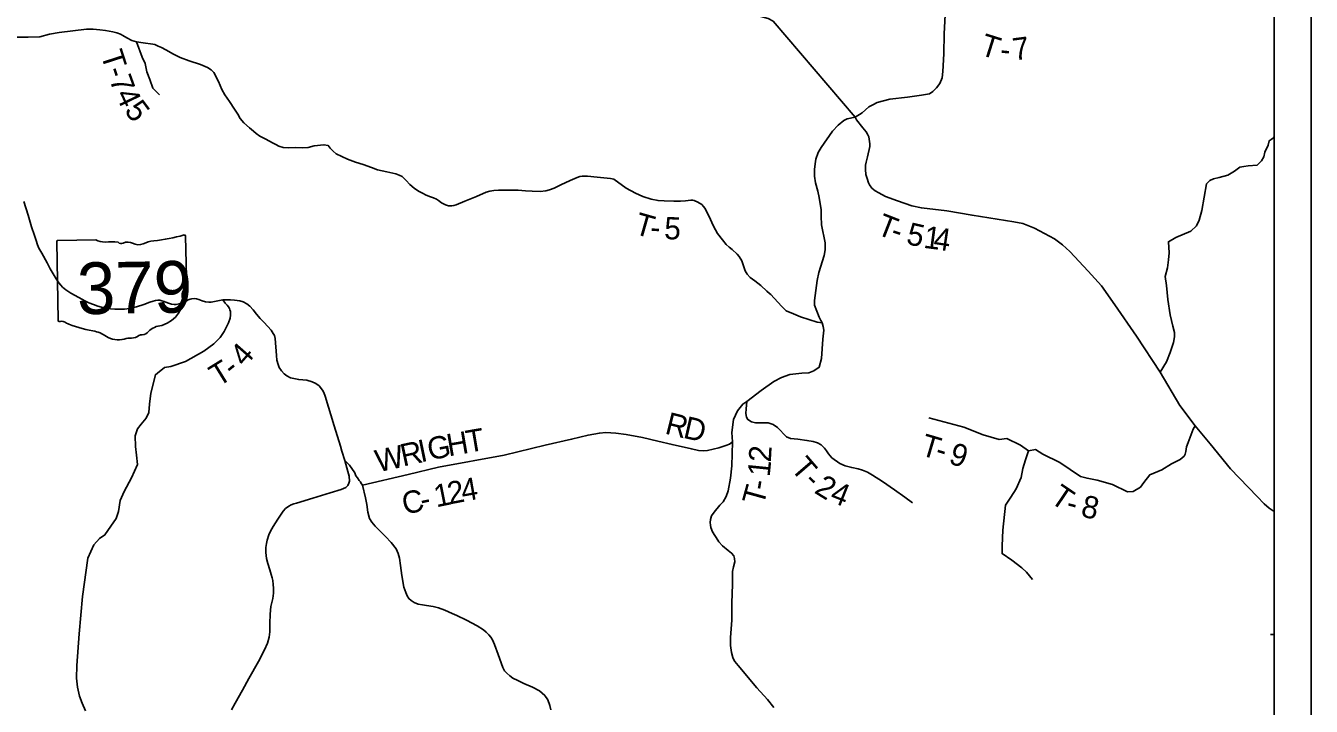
# Model space of a CAD drawing. Extents: x 0 to 2329303, y 0 to 694397.
# Drawn here: x 5.532 to 9, y 18.113 to 19.946 of the extents above; entities that cross this region are included whole.
import ezdxf

# ---------------------------------------------------------------- set-up
doc = ezdxf.new("R2010")
doc.units = 0
for name, color, linetype in [('GM_X_County_Road', 7, 'Continuous'), ('GM_X_County_Road_Text', 7, 'Continuous'), ('GM_X_State_Route', 7, 'Continuous'), ('GM_X_State_Shield', 7, 'Continuous'), ('GM_X_Township_Road', 7, 'Continuous'), ('GM_X_Township_Road_Text', 7, 'Continuous'), ('GM_X_Township_ROW', 7, 'Continuous'), ('SH_Data', 7, 'Continuous')]:
    doc.layers.add(name, color=color, linetype=linetype)

msp = doc.modelspace()

# ---------------------------------------------------------------- linework, layer by layer
at = {"layer": 'GM_X_County_Road'}
for points in [[(6.4411, 18.7082), (6.5643, 18.7373), (6.6462, 18.7565), (6.8229, 18.7894), (6.9332, 18.8158), (7.0048, 18.8321), (7.0492, 18.8434), (7.0798, 18.8488), (7.0976, 18.8503), (7.1241, 18.8485), (7.1519, 18.8452), (7.1959, 18.8363), (7.2372, 18.8271), (7.2758, 18.8178), (7.3279, 18.806), (7.3471, 18.8021), (7.3605, 18.8007), (7.3713, 18.8018), (7.4016, 18.809), (7.4211, 18.8147), (7.4309, 18.8185), (7.4389, 18.8248), (7.4371, 18.8504), (7.4416, 18.8853), (7.452, 18.9084), (7.4663, 18.9265), (7.4778, 18.9337), (7.5159, 18.9637), (7.5505, 18.9878), (7.5706, 18.9984), (7.5931, 19.0061), (7.6262, 19.0098), (7.645, 19.011), (7.6583, 19.0167), (7.6728, 19.0261), (7.6788, 19.0493), (7.6828, 19.1016), (7.6848, 19.1263), (7.6835, 19.1361), (7.6804, 19.1454), (7.6771, 19.1515), (7.6728, 19.1608), (7.6602, 19.1936), (7.66, 19.2056), (7.6675, 19.2595), (7.6713, 19.2815), (7.6857, 19.3268), (7.6891, 19.3425), (7.6885, 19.3495), (7.6885, 19.3609), (7.6791, 19.41), (7.6776, 19.4327), (7.6778, 19.45), (7.6728, 19.4836), (7.6687, 19.5005), (7.6626, 19.5231), (7.6599, 19.5409), (7.6603, 19.559), (7.6619, 19.5738), (7.6638, 19.5863), (7.6703, 19.6042), (7.6783, 19.6181), (7.7089, 19.6619), (7.7236, 19.678), (7.7389, 19.6904), (7.748, 19.6949), (7.7701, 19.7002), (7.7883, 19.7113), (7.8066, 19.7274), (7.8178, 19.7333), (7.8293, 19.7391), (7.8628, 19.7479), (7.9105, 19.7539), (7.9489, 19.7591), (7.9702, 19.763), (7.9794, 19.7693), (7.989, 19.7788), (7.9981, 19.7905), (8.0044, 19.8054), (8.0066, 19.8224), (8.0086, 19.8703), (8.0099, 19.9239), (8.0125, 19.9753)], [(6.4366, 18.7149), (6.4351, 18.7171), (6.4322, 18.7212), (6.4274, 18.7276), (6.423, 18.7334), (6.4199, 18.7414), (6.4124, 18.7531), (6.4056, 18.762), (6.3934, 18.7745)], [(6.9493, 18.1033), (6.9464, 18.1149), (6.9409, 18.1299), (6.9326, 18.1412), (6.918, 18.1541), (6.8994, 18.1643), (6.8758, 18.1739), (6.8596, 18.1816), (6.8467, 18.1883), (6.8381, 18.1942), (6.8298, 18.2018), (6.8242, 18.2084), (6.8196, 18.2174), (6.8071, 18.2518), (6.797, 18.2787), (6.7915, 18.2914), (6.7871, 18.2984), (6.7819, 18.3052), (6.7745, 18.3122), (6.7676, 18.3183), (6.7504, 18.3295), (6.7216, 18.3443), (6.6953, 18.3575), (6.6826, 18.3628), (6.6632, 18.3713), (6.6463, 18.3774), (6.6313, 18.3809), (6.6135, 18.3838), (6.603, 18.3854), (6.5908, 18.3879), (6.5801, 18.3919), (6.5719, 18.3974), (6.5657, 18.4028), (6.5612, 18.4104), (6.5574, 18.4186), (6.5523, 18.4332), (6.5468, 18.4648), (6.5431, 18.4922), (6.5408, 18.5118), (6.5374, 18.5243), (6.5316, 18.5363), (6.5182, 18.5536), (6.503, 18.5698), (6.4751, 18.5978), (6.4662, 18.6086), (6.4594, 18.6184), (6.4551, 18.6354), (6.4522, 18.6562), (6.4488, 18.6744), (6.4411, 18.7082), (6.4366, 18.7149)]]:
    msp.add_lwpolyline(points, dxfattribs=at)
at = {"layer": 'GM_X_State_Route'}
msp.add_lwpolyline([(6.0873, 18.103), (6.0973, 18.1213), (6.1169, 18.1562), (6.1341, 18.1876), (6.1601, 18.2332), (6.1768, 18.2642), (6.1843, 18.2824), (6.1887, 18.2988), (6.1905, 18.3133), (6.1911, 18.326), (6.1913, 18.3363), (6.1915, 18.36), (6.1923, 18.3716), (6.1939, 18.3812), (6.1988, 18.4025), (6.2006, 18.417), (6.2006, 18.4306), (6.2, 18.4408), (6.1986, 18.451), (6.1971, 18.4586), (6.1948, 18.4672), (6.1907, 18.4803), (6.1852, 18.4976), (6.1822, 18.5105), (6.181, 18.5184), (6.1801, 18.5269), (6.1799, 18.5406), (6.1816, 18.5511), (6.1834, 18.5598), (6.1881, 18.574), (6.1931, 18.5845), (6.2001, 18.597), (6.2124, 18.6164), (6.2271, 18.638), (6.2336, 18.6451), (6.2418, 18.6518), (6.2486, 18.6551), (6.2559, 18.6581), (6.2627, 18.66), (6.307, 18.6731), (6.3536, 18.6874), (6.3837, 18.6966), (6.3898, 18.6995), (6.3958, 18.7023), (6.4014, 18.7075), (6.4043, 18.7137), (6.4059, 18.7194), (6.405, 18.7323), (6.4014, 18.7449), (6.3985, 18.755), (6.3934, 18.7745), (6.3851, 18.8), (6.3811, 18.8133), (6.3649, 18.8678), (6.3404, 18.9477), (6.3364, 18.9575), (6.3328, 18.9645), (6.3239, 18.9755), (6.315, 18.9821), (6.3051, 18.9871), (6.2905, 18.9912), (6.2688, 18.9929), (6.2468, 18.9971), (6.2364, 19.0029), (6.2297, 19.0078), (6.2224, 19.016), (6.2163, 19.0251), (6.2131, 19.0332), (6.2097, 19.0455), (6.2086, 19.0579), (6.2051, 19.103), (6.2032, 19.1113), (6.2002, 19.1172), (6.1944, 19.1263), (6.1852, 19.1358), (6.1745, 19.1472), (6.1647, 19.1577), (6.1549, 19.1688), (6.1462, 19.1806), (6.1372, 19.1903), (6.1292, 19.1969), (6.1191, 19.202), (6.1098, 19.2047), (6.0958, 19.2067), (6.0845, 19.2078), (6.0721, 19.208), (6.0639, 19.2074), (6.0323, 19.2015), (6.0268, 19.2016), (6.0175, 19.2025), (6.0085, 19.2051), (5.9993, 19.2082), (5.9927, 19.21), (5.9869, 19.211), (5.9805, 19.2106), (5.976, 19.2095), (5.9711, 19.2074), (5.9649, 19.2041), (5.9535, 19.1993), (5.9467, 19.1968), (5.9386, 19.1953), (5.9329, 19.1952), (5.9254, 19.1959), (5.9175, 19.1987), (5.9103, 19.2013), (5.9057, 19.2032), (5.9, 19.2052), (5.894, 19.2066), (5.8885, 19.2066), (5.8829, 19.206), (5.8758, 19.2039), (5.8671, 19.2009), (5.8511, 19.1948), (5.8317, 19.1885), (5.8123, 19.1847), (5.7993, 19.1829), (5.7884, 19.1824), (5.7733, 19.1823), (5.7616, 19.1832), (5.7495, 19.185), (5.7367, 19.1876), (5.7273, 19.1907), (5.7151, 19.1948), (5.7026, 19.1999), (5.6917, 19.2052), (5.6757, 19.2138), (5.6539, 19.2257), (5.6403, 19.2347), (5.632, 19.2418), (5.6268, 19.2471), (5.6215, 19.2536), (5.6143, 19.2645), (5.5985, 19.2908), (5.5899, 19.3074), (5.5756, 19.3335), (5.5681, 19.3472), (5.564, 19.356), (5.5603, 19.3676), (5.5558, 19.3809), (5.5485, 19.4041), (5.5387, 19.4355), (5.5273, 19.4728)], dxfattribs=at)
at = {"layer": 'GM_X_State_Shield'}
for p, q in [((5.6161, 19.3641), (5.6196, 19.1528)), ((5.7214, 19.3695), (5.6195, 19.3678)), ((5.9658, 19.2683), (5.9639, 19.3789)), ((5.9658, 19.2683), (5.9658, 19.2683))]:
    msp.add_line(p, q, dxfattribs=at)
for centre, major_axis, start_param, end_param in [((5.6201, 19.3647), (0.00403, 0.00007), 1.712693, 3.28349), ((5.7452, 19.3945), (0.0391, 0.0007), 4.042523, 4.731795), ((5.7606, 19.2515), (0.1404, 0.0024), 1.404758, 1.657858), ((5.7905, 19.3686), (0.0113, 0.0002), 3.836095, 5.185415), ((5.8075, 19.3445), (0.0235, 0.0004), 0.950623, 2.079405), ((5.8372, 19.3785), (0.0282, 0.0005), 4.081561, 5.145723), ((5.8882, 19.3078), (0.0742, 0.0012), 1.699011, 2.107814), ((5.8352, 19.6596), (0.369, 0.0062), 4.814394, 5.042369), ((5.9601, 19.3792), (0.00387, 0.00006), 6.141152, 7.989035), ((5.965, 19.2602), (0.006, 0.0001), 1.883978, 3.671073), ((5.9271, 19.2456), (0.036, 0.0006), 5.934695, 6.695948), ((5.9617, 19.2678), (0.00415, 0.00007), 5.05454, 6.418171), ((5.8635, 19.2063), (0.0923, 0.0015), 5.101752, 6.440018), ((5.9804, 19.2223), (0.0262, 0.0004), 2.387724, 3.262537), ((5.6237, 19.1525), (0.00407, 0.00007), 3.00124, 4.508301), ((5.6239, 19.1741), (0.031, 0.0005), 4.665946, 4.897461), ((5.6308, 19.1408), (0.0112, 0.0002), 0.519207, 1.627899), ((5.7689, 19.3331), (0.2665, 0.0045), 4.195997, 4.488961), ((5.6941, 19.0591), (0.0834, 0.0014), 0.823519, 1.323587), ((5.7829, 19.1423), (0.0529, 0.0009), 4.026481, 4.996735), ((5.8176, 19.1271), (0.0282, 0.0005), 4.691044, 5.507374), ((5.8434, 19.1071), (0.00794, 0.00013), 1.147584, 2.315152), ((5.8396, 19.1361), (0.0298, 0.0005), 4.937069, 5.64225), ((5.9043, 19.0983), (0.0506, 0.0008), 1.647645, 2.488434), ((5.8147, 19.0698), (0.0435, 0.0007), 1.495662, 1.94098)]:
    msp.add_ellipse(centre, major_axis=major_axis, ratio=0.8, start_param=start_param, end_param=end_param, dxfattribs=at)
at = {"layer": 'GM_X_Township_Road'}
msp.add_line((8.9, 18.3061), (8.8904, 18.3062), dxfattribs=at)
for points in [[(5.8316, 19.9029), (5.8187, 19.9068), (5.8056, 19.9139), (5.7948, 19.92), (5.7881, 19.9235), (5.7783, 19.9269), (5.7671, 19.9301), (5.7476, 19.9336), (5.7327, 19.9354), (5.7148, 19.9371), (5.6967, 19.9367), (5.6229, 19.9279), (5.5968, 19.9235), (5.5703, 19.9167), (5.5393, 19.9154), (5.5174, 19.9154), (5.4998, 19.9151), (5.4893, 19.9096)], [(7.0336, 19.5405), (7.027, 19.54), (7.0202, 19.5376), (7.001, 19.5294), (6.9754, 19.5179), (6.958, 19.5088), (6.9456, 19.5038), (6.935, 19.5012), (6.9202, 19.4998), (6.8982, 19.5001), (6.8803, 19.5017), (6.8604, 19.503), (6.823, 19.5031), (6.8079, 19.503), (6.7952, 19.5025), (6.784, 19.5007), (6.7748, 19.4978), (6.7488, 19.4863), (6.717, 19.4731), (6.6939, 19.4638), (6.6871, 19.4618), (6.6811, 19.4607), (6.6726, 19.4609), (6.6651, 19.4636), (6.6536, 19.4693), (6.6456, 19.4755), (6.6403, 19.4786), (6.6321, 19.4824), (6.6246, 19.4851), (6.613, 19.4894), (6.6026, 19.4948), (6.5918, 19.5004), (6.5802, 19.5086), (6.5687, 19.5182), (6.5583, 19.5296), (6.5475, 19.5395), (6.5398, 19.5433), (6.5304, 19.5467), (6.5063, 19.5526), (6.4815, 19.5583), (6.4648, 19.5641), (6.4428, 19.5721), (6.4217, 19.5789), (6.4, 19.5863), (6.3698, 19.601), (6.362, 19.608), (6.354, 19.6165), (6.3483, 19.6233), (6.337, 19.6253), (6.3102, 19.6223), (6.294, 19.6183), (6.2797, 19.6172), (6.2612, 19.6179), (6.2412, 19.6176), (6.2267, 19.6184), (6.2155, 19.6215), (6.2069, 19.626), (6.1978, 19.6305), (6.1797, 19.6402), (6.1638, 19.6487), (6.1545, 19.6556), (6.1472, 19.6621), (6.136, 19.6712), (6.1208, 19.6849), (6.1111, 19.6966), (6.1048, 19.7078), (6.096, 19.7218), (6.0824, 19.742), (6.0696, 19.7604), (6.0618, 19.7741), (6.0525, 19.7959), (6.0396, 19.8199), (6.0328, 19.8277), (6.0228, 19.8332), (6.0041, 19.8414), (5.9733, 19.852), (5.9492, 19.8602), (5.9311, 19.8697), (5.9107, 19.8808), (5.8984, 19.8875), (5.8893, 19.8914), (5.8803, 19.8952), (5.875, 19.8968), (5.8493, 19.8998), (5.8316, 19.9029)], [(5.8316, 19.9029), (5.8465, 19.8615), (5.8544, 19.8446), (5.8593, 19.8215), (5.8669, 19.801), (5.875, 19.7776), (5.8933, 19.7603)], [(7.7701, 19.7002), (7.7735, 19.6924), (7.7906, 19.6709), (7.7995, 19.6603), (7.803, 19.6538), (7.8062, 19.6471), (7.8094, 19.6279), (7.8093, 19.6205), (7.8028, 19.5929), (7.7994, 19.5784), (7.7977, 19.5706), (7.7973, 19.5584), (7.7989, 19.5456), (7.8018, 19.5343), (7.806, 19.523), (7.8083, 19.5178), (7.8151, 19.5083), (7.8241, 19.5009), (7.8332, 19.4955), (7.8518, 19.4859), (7.8837, 19.474), (7.9229, 19.4607), (7.9485, 19.4552), (8.0169, 19.4473), (8.0849, 19.4357), (8.1974, 19.4182), (8.2223, 19.4131), (8.2537, 19.4003), (8.3072, 19.372), (8.3293, 19.3562), (8.3491, 19.3378), (8.3983, 19.285), (8.4341, 19.2456), (8.4698, 19.1944), (8.5288, 19.11), (8.5926, 19.0123), (8.6452, 18.9226), (8.6871, 18.868), (8.7269, 18.8193), (8.7825, 18.7522), (8.8538, 18.6778), (8.8729, 18.6578), (8.8866, 18.6464), (8.9, 18.6376)], [(8.8981, 19.6441), (8.892, 19.6399), (8.8866, 19.6362), (8.8835, 19.6244), (8.875, 19.6057), (8.8723, 19.5931), (8.8659, 19.582), (8.8544, 19.5707), (8.8296, 19.569), (8.8185, 19.5673), (8.8069, 19.5653), (8.7933, 19.5543), (8.7749, 19.5436), (8.7519, 19.5374), (8.7361, 19.534), (8.7266, 19.5296), (8.717, 19.52), (8.705, 19.4481), (8.6976, 19.4222), (8.6906, 19.4066), (8.6748, 19.3924), (8.635, 19.3752), (8.6146, 19.3643), (8.6166, 19.3343), (8.6153, 19.315), (8.6118, 19.294), (8.6055, 19.2701), (8.6095, 19.246), (8.6127, 19.2087), (8.6195, 19.1668), (8.6262, 19.1365), (8.6314, 19.1194), (8.6312, 19.1078), (8.6284, 19.0929), (8.6198, 19.0655), (8.6095, 19.0407), (8.5926, 19.0123)], [(8.9, 19.6473), (8.8983, 19.6443), (8.8981, 19.6441)], [(7.5387, 19.2248), (7.5312, 19.231), (7.5154, 19.2461), (7.4995, 19.2589), (7.4869, 19.2677), (7.4786, 19.2764), (7.4731, 19.2855), (7.4693, 19.2964), (7.4669, 19.3047), (7.4641, 19.3131), (7.4569, 19.3247), (7.451, 19.3308), (7.4377, 19.3435), (7.4296, 19.3496), (7.4219, 19.3565), (7.4119, 19.369), (7.398, 19.3859), (7.3875, 19.4062), (7.3747, 19.4336), (7.3642, 19.4542), (7.3605, 19.4595), (7.3562, 19.4644), (7.3453, 19.4712), (7.3354, 19.4755), (7.3311, 19.4765), (7.3262, 19.4766), (7.3124, 19.4747), (7.2983, 19.4731), (7.2802, 19.4739), (7.2541, 19.4742), (7.2381, 19.4751), (7.2194, 19.479), (7.1972, 19.4857), (7.177, 19.4949), (7.1523, 19.5081), (7.119, 19.5326), (7.1097, 19.5348), (7.0734, 19.5385), (7.048, 19.5404), (7.0358, 19.5407), (7.0336, 19.5405)], [(7.6804, 19.1454), (7.667, 19.1471), (7.6221, 19.162), (7.6034, 19.1695), (7.5839, 19.178), (7.5707, 19.1903), (7.5423, 19.2219), (7.5387, 19.2248)], [(6.0639, 19.2074), (6.0708, 19.1986), (6.0754, 19.1932), (6.079, 19.189), (6.0819, 19.1844), (6.0834, 19.1806), (6.0847, 19.1758), (6.0851, 19.1707), (6.0849, 19.1659), (6.0836, 19.1583), (6.0792, 19.1458), (6.068, 19.1224), (6.0572, 19.1057), (6.0399, 19.089), (6.0131, 19.0691), (5.9632, 19.0418), (5.9243, 19.0278), (5.9069, 19.0249), (5.8881, 19.0101), (5.8823, 19.0058), (5.8702, 18.9564), (5.8666, 18.9261), (5.8647, 18.9044), (5.8573, 18.8885), (5.8435, 18.8727), (5.8336, 18.8603), (5.8275, 18.8412), (5.8287, 18.8127), (5.8316, 18.7895), (5.8338, 18.7639), (5.8176, 18.728), (5.7978, 18.6915), (5.7872, 18.6666), (5.7823, 18.6372), (5.7767, 18.6185), (5.7619, 18.5978), (5.746, 18.5744), (5.7319, 18.5646), (5.7166, 18.5475), (5.7, 18.5116), (5.6856, 18.4079), (5.6764, 18.3081), (5.6705, 18.222), (5.6699, 18.1879), (5.672, 18.1643), (5.6778, 18.1393), (5.6849, 18.1207), (5.6941, 18.1002)], [(7.4778, 18.9337), (7.4754, 18.9139), (7.4745, 18.9015), (7.4763, 18.8913), (7.4805, 18.8849), (7.4898, 18.8786), (7.5009, 18.8758), (7.5211, 18.8761), (7.5349, 18.8758), (7.5482, 18.8717), (7.5599, 18.8633), (7.5843, 18.8386), (7.5949, 18.8342), (7.6147, 18.8326), (7.6398, 18.8288), (7.6566, 18.8259), (7.6685, 18.8221), (7.6778, 18.8169), (7.687, 18.8082), (7.6924, 18.8011), (7.698, 18.793), (7.707, 18.7815), (7.7285, 18.767), (7.7425, 18.7602), (7.7606, 18.7556), (7.7778, 18.752), (7.7897, 18.749), (7.8027, 18.7432), (7.8165, 18.7355), (7.8433, 18.7181), (7.8762, 18.6953), (7.9034, 18.6763), (7.9245, 18.6604)], [(7.9681, 18.8897), (8.0632, 18.8645), (8.1149, 18.8441), (8.1578, 18.8309), (8.179, 18.8337), (8.2153, 18.8159), (8.2375, 18.8011)], [(8.6871, 18.868), (8.6812, 18.8595), (8.6677, 18.8231), (8.6635, 18.8112), (8.6616, 18.7986), (8.66, 18.7918), (8.657, 18.786), (8.6461, 18.7773), (8.6234, 18.7653), (8.5966, 18.75), (8.5645, 18.7357), (8.5481, 18.7154), (8.5389, 18.703), (8.5198, 18.691), (8.5046, 18.69), (8.4634, 18.7101), (8.4229, 18.7217), (8.3954, 18.7271), (8.3772, 18.7316), (8.3217, 18.7695), (8.2755, 18.7914), (8.2562, 18.8043), (8.2375, 18.8011), (8.2293, 18.7763), (8.2218, 18.7536), (8.2175, 18.7289), (8.2043, 18.6987), (8.2041, 18.6984)], [(7.4389, 18.8248), (7.4374, 18.7605), (7.4337, 18.7273), (7.4269, 18.6934), (7.4217, 18.6776), (7.4133, 18.6635), (7.4049, 18.6542), (7.3892, 18.6358), (7.3824, 18.626), (7.3793, 18.6154), (7.3786, 18.6076), (7.3792, 18.6008), (7.3805, 18.594), (7.3848, 18.5828), (7.3991, 18.5603)], [(8.2041, 18.6984), (8.1892, 18.6757), (8.1748, 18.6547), (8.1682, 18.587), (8.1663, 18.5448), (8.1659, 18.5239), (8.1919, 18.5061), (8.2195, 18.4851), (8.232, 18.474), (8.2484, 18.4538)], [(7.3991, 18.5603), (7.4021, 18.5555), (7.4122, 18.5449), (7.4271, 18.5319), (7.4365, 18.5251), (7.4423, 18.5177), (7.4445, 18.5104), (7.4449, 18.5014), (7.4419, 18.4885), (7.4391, 18.4759), (7.4388, 18.4413), (7.4372, 18.3904), (7.4368, 18.3445), (7.4333, 18.2978), (7.4338, 18.2765), (7.4362, 18.2574), (7.4398, 18.2437), (7.4447, 18.2341), (7.4453, 18.2333)], [(7.4453, 18.2333), (7.4537, 18.2222), (7.5048, 18.1624), (7.5331, 18.1304), (7.5504, 18.1095)]]:
    msp.add_lwpolyline(points, dxfattribs=at)
at = {"layer": 'GM_X_Township_ROW'}
msp.add_lwpolyline([(7.5028, 19.9739), (7.5153, 19.9712), (7.5255, 19.9681), (7.5352, 19.9654), (7.5487, 19.9583), (7.7701, 19.7002)], dxfattribs=at)
at = {"layer": 'SH_Data'}
for points in [[(2, 21), (9, 21), (9, 14), (2, 14)], [(2.1, 20.9), (8.9, 20.9), (8.9, 14.1), (2.1, 14.1)]]:
    msp.add_lwpolyline(points, close=True, dxfattribs=at)

# ---------------------------------------------------------------- texts
at = {"layer": 'GM_X_County_Road_Text'}
for s, rotation, p in [('R', 345.9212, (7.2539, 18.8477)), ('D', 347.1534, (7.3033, 18.8362)), ('I', 11.7769, (6.5981, 18.7695)), ('G', 10.7734, (6.6219, 18.7749)), ('H', 9.8067, (6.6733, 18.7856)), ('T', 9.7195, (6.7252, 18.7954)), ('W', 12.1591, (6.4825, 18.7426)), ('R', 12.1351, (6.5502, 18.7584)), ('4', 9.9371, (6.7118, 18.6637)), ('C', 11.959, (6.5542, 18.6284)), ('1', 11.3936, (6.6399, 18.6483)), ('2', 10.7629, (6.6758, 18.6562)), ('-', 11.7998, (6.6022, 18.6394))]:
    msp.add_text(s, height=0.06, rotation=rotation, dxfattribs=at).set_placement(p)
at = {"layer": 'GM_X_State_Shield'}
msp.add_text('379', height=0.13922, rotation=0.961, dxfattribs=at).set_placement((5.6717, 19.1686))
at = {"layer": 'GM_X_Township_Road_Text'}
for s, rotation, p in [('T', 342.591, (8.103, 19.8689)), ('7', 7.4896, (8.1983, 19.8523)), ('T', 287.8807, (5.734, 19.8694)), ('-', 354.4397, (8.1591, 19.8538)), ('7', 290.0325, (5.7575, 19.8013)), ('-', 288.3175, (5.7487, 19.8264)), ('4', 295.6491, (5.7733, 19.7609)), ('5', 306.773, (5.7966, 19.7172)), ('T', 344.0364, (7.1708, 19.3864)), ('5', 357.5471, (7.2538, 19.3715)), ('T', 338.7111, (7.824, 19.3859)), ('-', 356.4484, (7.2158, 19.374)), ('-', 341.0913, (7.8617, 19.3711)), ('5', 347.0167, (7.9049, 19.3588)), ('1', 352.5147, (7.9521, 19.348)), ('4', 351.6175, (7.9787, 19.3447)), ('4', 48.7838, (6.1231, 19.0247)), ('T', 31.7333, (6.0518, 18.9719)), ('-', 39.033, (6.091, 18.9981)), ('T', 343.5224, (7.9428, 18.7902)), ('2', 86.6886, (7.5422, 18.7689)), ('-', 343.2611, (7.9823, 18.7794)), ('9', 341.6671, (8.0191, 18.7679)), ('1', 84.3061, (7.539, 18.7293)), ('T', 310.6654, (7.5935, 18.7525)), ('-', 315.4085, (7.6271, 18.7151)), ('2', 328.4307, (7.6567, 18.6891)), ('T', 74.5709, (7.522, 18.6506)), ('-', 79.9383, (7.5325, 18.6918)), ('4', 337.9128, (7.6983, 18.6656)), ('T', 325.8618, (8.2922, 18.6643)), ('-', 345.2623, (8.3357, 18.635)), ('8', 346.9595, (8.3758, 18.6247))]:
    msp.add_text(s, height=0.06, rotation=rotation, dxfattribs=at).set_placement(p)

doc.saveas('drawing.dxf')
